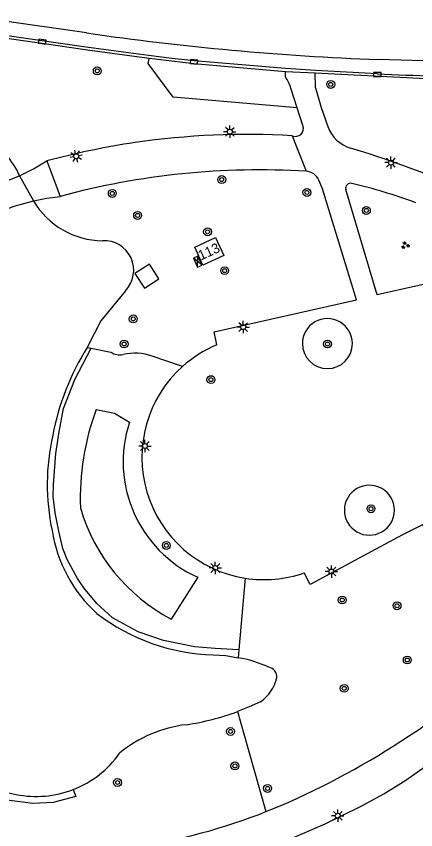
# Model space of a CAD drawing. Extents: x 132998 to 136004, y 396998 to 398512.
# Drawn here: x 133634.6 to 133674.9, y 397524.1 to 397606.3 of the extents above; entities that cross this region are included whole.
import ezdxf

# ---------------------------------------------------------------- set-up
doc = ezdxf.new("R2010")
doc.units = 0
for name, color, linetype in [('gg-anno-huisnummerreeks BGT', 7, 'Continuous'), ('gg-bbg-hoofdgebouw', 7, 'Continuous'), ('gg-knt-onverhard', 7, 'Continuous'), ('gg-knt-verharding', 7, 'Continuous'), ('gg-knt-verharding nz', 7, 'Continuous'), ('gg-kntw-beschoeiing', 7, 'Continuous'), ('gg-kwrk-betonelement', 7, 'Continuous'), ('gg-kwrk-kunstwerk niveau 01', 7, 'Continuous'), ('gt-grn-groengrens', 7, 'Continuous'), ('gt-grn-weggrens', 7, 'Continuous'), ('gt-symb-boom', 7, 'Continuous'), ('gt-symb-elektrakast', 7, 'Continuous'), ('gt-symb-groenvak', 7, 'Continuous'), ('gt-symb-kolk', 7, 'Continuous'), ('gt-symb-lichtmast', 7, 'Continuous')]:
    doc.layers.add(name, color=color, linetype=linetype)

# ---------------------------------------------------------------- blocks, each defined once
blk = doc.blocks.new('gt0-KOLK')
at = {"layer": 'gt-symb-kolk'}
blk.add_lwpolyline([(0, 0), (0.375, 0), (0.375, 0.4), (-0.375, 0.4), (-0.375, 0), (0, 0)], dxfattribs=at)
blk = doc.blocks.new('gt0-BOOM')
at = {"layer": 'gt-symb-boom'}
for radius in [0.4, 0.2]:
    blk.add_circle((0, 0), radius, dxfattribs=at)
blk = doc.blocks.new('gt0-LMAST')
at = {"layer": 'gt-symb-lichtmast'}
for p, q in [((-0.182, 0.173), (-0.447, 0.438)), ((-0.005, 0.246), (-0.005, 0.621)), ((0.172, 0.173), (0.437, 0.438)), ((-0.255, -0.004), (-0.63, -0.004)), ((-0.182, -0.181), (-0.447, -0.446)), ((-0.005, -0.254), (-0.005, -0.629)), ((0.437, -0.446), (0.172, -0.181)), ((0.245, -0.004), (0.62, -0.004))]:
    blk.add_line(p, q, dxfattribs=at)
blk.add_circle((-0.005, -0.004), 0.25, dxfattribs=at)
blk = doc.blocks.new('gt0-EKAST')
at = {"layer": 'gt-symb-elektrakast'}
for p, q in [((-0.501, -0.249), (0.501, 0.249)), ((-0.501, 0.249), (0.501, -0.249))]:
    blk.add_line(p, q, dxfattribs=at)
blk.add_lwpolyline([(0.501, 0.249), (-0.501, 0.249), (-0.501, -0.249), (0.501, -0.249)], close=True, dxfattribs=at)
blk = doc.blocks.new('gt0-GRVAK')
at = {"layer": 'gt-symb-groenvak'}
for p, q in [((-0.11, 0.189), (-0.228, 0.24)), ((-0.182, 0.153), (0.088, 0.153)), ((-0.091, 0.211), (-0.156, 0.322)), ((-0.047, 0.214), (-0.047, 0.393)), ((-0.004, 0.211), (0.061, 0.322)), ((0.015, 0.189), (0.133, 0.24)), ((0.262, -0.052), (0.197, 0.059)), ((0.305, -0.049), (0.305, 0.13)), ((0.349, -0.052), (0.414, 0.059)), ((-0.245, -0.228), (-0.363, -0.177)), ((-0.318, -0.264), (-0.047, -0.264)), ((-0.226, -0.206), (-0.291, -0.095)), ((-0.183, -0.203), (-0.183, -0.024)), ((-0.139, -0.206), (-0.074, -0.095)), ((-0.12, -0.228), (-0.002, -0.177)), ((0.243, -0.074), (0.125, -0.023)), ((0.17, -0.11), (0.441, -0.11)), ((0.368, -0.074), (0.486, -0.023))]:
    blk.add_line(p, q, dxfattribs=at)

msp = doc.modelspace()

# ---------------------------------------------------------------- linework, layer by layer
at = {"layer": 'gg-bbg-hoofdgebouw'}
msp.add_lwpolyline([(133653.42, 397581.2), (133652.59, 397583.02), (133654.69, 397583.98), (133655.51, 397582.16), (133653.42, 397581.2)], dxfattribs=at)
at = {"layer": 'gg-knt-onverhard'}
msp.add_line((133659.781, 397525.944), (133661.232, 397526.532), dxfattribs=at)
for points in [[(133664.781, 397599.102), (133665.35, 397597.133), (133666.02, 397595.197)], [(133654.833, 397573.147), (133654.537, 397574.46), (133668.935, 397577.684), (133665.511, 397588.918), (133665.118, 397589.794)], [(133683.662, 397581.029), (133671.004, 397578.175), (133667.855, 397588.827)], [(133679.513, 397538.061), (133675.657, 397554.97), (133673.579, 397553.934), (133664.262, 397548.903), (133663.656, 397550.084)], [(133653.301, 397519.826), (133657.7, 397521.38), (133662.042, 397523.089), (133665.749, 397524.718), (133669.391, 397526.489), (133671.692, 397527.73), (133673.911, 397529.112), (133677.019, 397531.322), (133680.02, 397533.676)]]:
    msp.add_lwpolyline(points, dxfattribs=at)
for centre, radius, start, end in [((133662.752, 397595.01), 0.811, 247.5117, 22.27188), ((133669.387, 397596.458), 3.595, 200.53651, 253.05524), ((133657.804, 397517.199), 77.2, 86.5556, 98.37089), ((133657.773, 397517.333), 77.063, 98.36282, 105.14453), ((133635.115, 397484.18), 113.797, 61.85269, 73.02495), ((133659.147, 397513.672), 77.148, 86.51193, 105.14615), ((133663.752, 397589.183), 1.497, 24.0939, 86.58114), ((133668.334, 397588.969), 0.499, 75.38356, 196.47955), ((133655.296, 397534.281), 56.719, 69.76452, 76.57979), ((133659.595, 397561.754), 12.348, 112.68549, 131.94848), ((133659.598, 397561.751), 12.353, 131.9478, 261.06202), ((133659.596, 397561.762), 12.364, 261.0794, 289.16943), ((133660.932, 397554.66), 24.916, 302.16981, 318.22361), ((133627.508, 397604.124), 84.604, 293.49139, 303.49521), ((133636.113, 397586.525), 65.04, 279.2516, 291.33935)]:
    msp.add_arc(centre, radius, start, end, dxfattribs=at)
at = {"layer": 'gg-knt-verharding'}
for p, q in [((133661.749, 397600.236), (133661.766, 397600.744)), ((133664.749, 397600.585), (133661.766, 397600.744)), ((133664.781, 397599.102), (133664.749, 397600.585)), ((133662.926, 397597.086), (133662.309, 397599.073)), ((133663.503, 397595.317), (133662.926, 397597.086))]:
    msp.add_line(p, q, dxfattribs=at)
for points in [[(133671.057, 397600.527), (133664.776, 397600.868), (133661.772, 397601.055), (133652.53, 397601.832), (133650.281, 397602.067), (133647.93, 397602.375), (133641.847, 397603.206), (133561.519, 397614.741)], [(133647.972, 397602.085), (133641.747, 397602.913), (133637.142, 397603.582), (133621.747, 397605.79), (133594.044, 397609.739), (133581.68, 397611.541)], [(133662.926, 397597.086), (133650.395, 397598.169), (133647.88, 397601.564), (133647.972, 397602.085)], [(133661.766, 397600.744), (133652.504, 397601.556), (133650.287, 397601.796), (133647.972, 397602.085)], [(133686.229, 397599.841), (133682.533, 397599.857), (133675.29, 397600.053), (133664.749, 397600.585)]]:
    msp.add_lwpolyline(points, dxfattribs=at)
for centre, radius, start, end in [((133657.027, 397597.246), 5.589, 19.07981, 32.34306), ((133701.336, 398299.546), 699.675, 267.519682, 268.460686)]:
    msp.add_arc(centre, radius, start, end, dxfattribs=at)
at = {"layer": 'gg-knt-verharding nz'}
msp.add_line((133641.636, 397604.658), (133561.759, 397616.13), dxfattribs=at)
msp.add_lwpolyline([(133686.212, 397601.588), (133682.568, 397601.639), (133671.118, 397601.963)], dxfattribs=at)
msp.add_arc((133682.064, 397884.314), 282.563, 261.77412, 267.77991, dxfattribs=at)
at = {"layer": 'gg-kntw-beschoeiing'}
msp.add_line((133634.888, 397590.23), (133636.283, 397587.704), dxfattribs=at)
msp.add_line((133634.888, 397590.23), (133636.283, 397587.704), dxfattribs=at)
for points in [[(133645.58, 397578.59), (133643.091, 397575.557), (133641.711, 397572.862)], [(133645.58, 397578.59), (133643.091, 397575.557), (133641.711, 397572.862)], [(133654.464, 397541.8), (133655.721, 397541.717), (133656.962, 397541.506)], [(133654.464, 397541.8), (133655.721, 397541.717), (133656.962, 397541.506)], [(133659.244, 397537.049), (133658.086, 397536.526), (133656.902, 397536.058)], [(133659.244, 397537.049), (133658.086, 397536.526), (133656.902, 397536.058)]]:
    msp.add_lwpolyline(points, dxfattribs=at)
for centre, radius, start, end in [((133626.413, 397586.348), 9.322, 24.61156, 56.69958), ((133626.413, 397586.348), 9.322, 24.61156, 56.69958), ((133643.346, 397591.851), 8.191, 210.42026, 269.43998), ((133643.346, 397591.851), 8.191, 210.42026, 269.43998), ((133643.422, 397580.669), 2.996, 316.06614, 92.99021), ((133643.422, 397580.669), 2.996, 316.06614, 92.99021), ((133663.818, 397559.095), 26.043, 148.0878, 169.17777), ((133663.818, 397559.095), 26.043, 148.0878, 169.17777), ((133660.118, 397559.014), 22.438, 167.20067, 192.00266), ((133660.118, 397559.014), 22.438, 167.20067, 192.00266), ((133652.348, 397556.611), 14.357, 189.06973, 227.79187), ((133652.348, 397556.611), 14.357, 189.06973, 227.79187), ((133654.996, 397561.944), 20.151, 232.40708, 268.48723), ((133654.996, 397561.944), 20.151, 232.40708, 268.48723), ((133654.809, 397528.987), 12.702, 65.55405, 80.24309), ((133654.809, 397528.987), 12.702, 65.55405, 80.24309), ((133659.847, 397539.54), 1.035, 357.25115, 77.8077), ((133659.847, 397539.54), 1.035, 357.25115, 77.8077), ((133656.828, 397540.438), 4.162, 305.47774, 346.82853), ((133656.828, 397540.438), 4.162, 305.47774, 346.82853), ((133640.18, 397558.005), 30.841, 221.84949, 259.48865), ((133640.18, 397558.005), 30.841, 221.84949, 259.48865), ((133647.772, 397560.911), 26.477, 278.63221, 290.17121), ((133647.772, 397560.911), 26.477, 278.63221, 290.17121), ((133653.241, 397521.877), 12.944, 96.63376, 129.581), ((133653.241, 397521.877), 12.944, 96.63376, 129.581), ((133636.579, 397537.767), 10.286, 291.19328, 324.90212), ((133636.579, 397537.767), 10.286, 291.19328, 324.90212), ((133636.578, 397537.765), 10.284, 258.65113, 291.20138), ((133636.578, 397537.765), 10.284, 258.65113, 291.20138)]:
    msp.add_arc(centre, radius, start, end, dxfattribs=at)
at = {"layer": 'gg-kwrk-betonelement'}
msp.add_lwpolyline([(133646.528, 397580.346), (133647.499, 397578.876), (133648.971, 397579.814), (133648, 397581.284), (133646.528, 397580.346)], dxfattribs=at)
at = {"layer": 'gg-kwrk-kunstwerk niveau 01'}
msp.add_line((133637.64, 397591.72), (133638.99, 397588.14), dxfattribs=at)
for points in [[(133634.888, 397590.23), (133636.292, 397590.924), (133637.64, 397591.72)], [(133631.217, 397588.974), (133633.082, 397589.517), (133634.888, 397590.23)], [(133632.463, 397586.436), (133634.343, 397587.161), (133636.283, 397587.704)], [(133636.283, 397587.704), (133637.629, 397587.966), (133638.99, 397588.14)]]:
    msp.add_lwpolyline(points, dxfattribs=at)
at = {"layer": 'gt-grn-groengrens'}
for p, q in [((133641.711, 397572.862), (133642.119, 397572.784)), ((133642.119, 397572.784), (133644.121, 397572.399)), ((133651.341, 397570.938), (133648.293, 397571.993)), ((133652.883, 397549.643), (133650.194, 397545.405)), ((133657.679, 397549.548), (133657.034, 397542.313)), ((133657.034, 397542.313), (133656.962, 397541.506)), ((133656.902, 397536.058), (133659.781, 397525.944))]:
    msp.add_line(p, q, dxfattribs=at)
for points in [[(133657.034, 397542.313), (133654.645, 397542.422), (133652.565, 397542.62), (133649.429, 397543.247), (133646.855, 397544.105), (133644.28, 397545.525), (133642.696, 397546.977), (133641.375, 397548.561), (133640.748, 397549.519), (133639.692, 397551.433), (133639.263, 397552.555), (133638.867, 397554.305), (133638.471, 397556.153), (133638.273, 397557.804), (133638.306, 397559.025), (133638.537, 397562.161), (133638.9, 397564.339), (133639.329, 397566.683), (133640.484, 397569.621), (133642.119, 397572.784)], [(133642.625, 397566.584), (133644.484, 397566.236), (133645.985, 397565.308)], [(133640.297, 397528.177), (133640.572, 397527.469), (133638.282, 397526.854), (133636.233, 397526.752), (133632.816, 397527.196)]]:
    msp.add_lwpolyline(points, dxfattribs=at)
for centre, radius, start, end in [((133665.989, 397573.256), 2.527, 359.98863, 180.01137), ((133665.989, 397573.256), 2.527, 180.01134, 359.98866), ((133644.962, 397573.5), 1.385, 232.64288, 285.77121), ((133646.497, 397566.668), 5.62, 71.36088, 101.89938), ((133666.349, 397557.708), 25.33, 159.4871, 182.39175), ((133658.173, 397561.323), 12.822, 161.89568, 245.6364), ((133670.234, 397556.42), 2.527, 359.98866, 180.01134), ((133658.88, 397561.822), 18.573, 196.16573, 242.11783), ((133670.234, 397556.419), 2.527, 179.98866, 0.01134)]:
    msp.add_arc(centre, radius, start, end, dxfattribs=at)
at = {"layer": 'gt-grn-weggrens'}
msp.add_line((133662.442, 397594.26), (133663.841, 397590.677), dxfattribs=at)

# ---------------------------------------------------------------- block references
at = {"layer": 'gt-symb-boom'}
for p, rotation in [((133642.741, 397600.826), -93.95503763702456), ((133674.063, 397541.273), -77.17287657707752)]:
    msp.add_blockref('gt0-BOOM', p, dxfattribs=dict(at, rotation=rotation))
for p in [(133666.326, 397599.458), (133655.312, 397589.841), (133644.257, 397588.438), (133663.921, 397588.534), (133669.927, 397586.715), (133646.817, 397586.219), (133653.88, 397584.557), (133655.608, 397580.629), (133646.374, 397575.756), (133645.451, 397573.217), (133666.001, 397573.219), (133654.217, 397569.614), (133670.394, 397556.562), (133649.715, 397552.852), (133667.486, 397547.338), (133673.025, 397546.759), (133667.69, 397538.408), (133656.2, 397534.047), (133656.648, 397530.564), (133644.785, 397528.889), (133659.95, 397528.288)]:
    msp.add_blockref('gt0-BOOM', p, dxfattribs=at)
at = {"layer": 'gt-symb-elektrakast', "rotation": 114.51474799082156}
msp.add_blockref('gt0-EKAST', (133652.894, 397581.548), dxfattribs=at)
at = {"layer": 'gt-symb-groenvak'}
msp.add_blockref('gt0-GRVAK', (133673.846, 397583.189), dxfattribs=at)
at = {"layer": 'gt-symb-kolk'}
for p, rotation in [((133637.142, 397603.582), -8.260210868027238), ((133652.504, 397601.556), -5.009587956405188)]:
    msp.add_blockref('gt0-KOLK', p, dxfattribs=dict(at, rotation=rotation))
msp.add_blockref('gt0-KOLK', (133671.035, 397600.265), dxfattribs=at)
at = {"layer": 'gt-symb-lichtmast'}
for p in [(133656.13, 397594.678), (133672.416, 397591.553), (133657.488, 397574.933), (133647.552, 397562.91), (133654.669, 397550.578), (133666.393, 397550.218), (133667.046, 397525.531)]:
    msp.add_blockref('gt0-LMAST', p, dxfattribs=at)
at = {"layer": 'gt-symb-lichtmast', "rotation": 13.07324828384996}
msp.add_blockref('gt0-LMAST', (133640.602, 397592.206), dxfattribs=at)

# ---------------------------------------------------------------- texts
at = {"layer": 'gg-anno-huisnummerreeks BGT'}
msp.add_text('113', height=1, rotation=24.6, dxfattribs=at).set_placement((133653.204, 397581.65))

doc.saveas('drawing.dxf')
